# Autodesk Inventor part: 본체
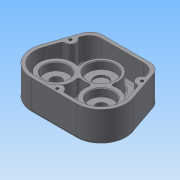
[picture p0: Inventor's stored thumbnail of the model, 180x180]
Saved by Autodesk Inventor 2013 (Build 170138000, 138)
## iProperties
Created: 2014-12
Part Number: 본체
Material: 일반
Document SubType Name: Modeling
Designer: Administrator
Density: 1 g/cm^3
Author: Administrator
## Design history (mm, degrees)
sketch "스케치1"
  geometry: L1 (0, 0)-(-32.527, -32.527); L2 (0, 0)-(32.527, -32.527); L3 (0, 0)-(0, -46); L4 (-47, 36)-(47, 36); L5 (-32.527, -68.527)-(32.527, -68.527); L6 (47, 36)-(66.565, -20.803); L7 (-47, 36)-(-66.565, -20.803); A1 r 46 centre (0, 0) between (-32.527, -32.527) and (32.527, -32.527); A2 r 36 centre (32.527, -32.527) between (32.527, -68.527) and (66.565, -20.803); A3 r 36 centre (-32.527, -32.527) between (-66.565, -20.803) and (-32.527, -68.527); 2 further points
  constraints: 14 end point, 7 point on circle, 3 centre point, 3 coincident, 3 tangent, 1 midpoint, 1 parallel, 1 perpendicular, 1 vertical, 1 vertical alignment
  dimensions: "d2" = 92 diameter of A1; "d3" = 90 deg angle of L2 L1; "d5" = 45 deg angle of L3 L1; "d9" = 94 distance of L4.start L4.end; "d10" = 36 distance from line of L4 point (0, 0)
extrude "돌출1" new body sketch "스케치1" distance "d11" = 44; taper "d12" = 0 deg
fillet "모깎기1" dims "d13" = 18
fillet "모깎기3" dims "d15" = 3
sketch "스케치27"
  geometry: L1 (-66.565, -20.803)-(-51.181, 23.862) reference; L2 (51.181, 23.862)-(66.565, -20.803) reference; L3 (-34.162, 36)-(34.162, 36) reference; L4 (-43.434, 31)-(-61.837, -22.432); L5 (43.434, 31)-(61.837, -22.432); L6 (-32.527, -63.527)-(32.527, -63.527); L7 (-43.434, 31)-(43.434, 31); L8 (-34.162, 36)-(34.162, 36) reference; L9 (51.181, 23.862)-(66.565, -20.803) reference; L10 (32.527, -68.527)-(-32.527, -68.527) reference; L11 (-66.565, -20.803)-(-51.181, 23.862) reference; A1 r 36 centre (-32.527, -32.527) between (-66.565, -20.803) and (-32.527, -68.527) reference; A2 r 36 centre (32.527, -32.527) between (32.527, -68.527) and (66.565, -20.803) reference; A3 r 31 centre (32.527, -32.527) between (32.527, -63.527) and (61.837, -22.432); A4 r 31 centre (-32.527, -32.527) between (-61.837, -22.432) and (-32.527, -63.527); A5 r 18 centre (-34.162, 18) between (-34.162, 36) and (-51.181, 23.862) reference; A6 r 18 centre (34.162, 18) between (51.181, 23.862) and (34.162, 36) reference; A7 r 36 centre (32.527, -32.527) between (32.527, -68.527) and (66.565, -20.803) reference; A8 r 36 centre (-32.527, -32.527) between (-66.565, -20.803) and (-32.527, -68.527) reference; 3 further points
  constraints: 8 end point, 4 point on circle, 4 tangent, 3 coincident, 2 centre point, 2 parallel, 1 midpoint, 1 vertical alignment
  dimensions: "d88" = 62 diameter of A3; "d90" = 62 diameter of A4; "d93" = 5 distance from line of L1 L4.start; "d94" = 5 distance from line of L3 point (0, 31); "d95" = 43.43386 distance of L5.start point (0, 31)
extrude "돌출17" cut sketch "스케치27" distance "d96" = 34; taper "d97" = 0 deg
fillet "모깎기5" dims "d98" = 18
sketch "스케치35"
  geometry: L1 (-61.837, -22.432)-(-47.615, 18.862) reference; L2 (-34.162, 36)-(34.162, 36) reference; A1 r 8 centre (-51.7, 7) between (-54.305, -0.564) and (-49.095, 14.564); 1 further point
  constraints: 3 point on line, 2 point on circle, 1 centre point
  dimensions: "d114" = 16 diameter of A1; "d115" = 29 distance from line of L2 A1.centre
extrude "돌출23" join sketch "스케치35" stored distance "d116" = 3; taper "d117" = 0 deg
sketch "스케치36"
  geometry: L1 (32.527, -63.527)-(-32.527, -63.527) reference; A1 r 8 centre (0, -63.527) between (8, -63.527) and (-8, -63.527); 1 further point
  constraints: 2 point on circle, 2 point on line, 1 centre point, 1 midpoint
  dimensions: "d118" = 16 diameter of A1
extrude "돌출24" join sketch "스케치36" stored distance "d119" = 3; taper "d120" = 0 deg
hole "구멍3" diameter "d123" = 4.134; stored, may be unused: countersink angle "d127" = 90 deg, drill point angle "d129" = 118 deg; dims "d121" = 10, "d122" = 10, "d124" = 20, "d125" = 4, "d126" = 2, "d128" = 23
hole "구멍4" diameter "d132" = 4.134; stored, may be unused: countersink angle "d136" = 90 deg, drill point angle "d138" = 118 deg; dims "d130" = 10, "d131" = 10, "d133" = 20, "d134" = 4, "d135" = 2, "d137" = 23
sketch "스케치37"
  geometry: C1 r 20 at (-32.527, -32.527); A1 r 33 centre (-32.527, -32.527) between (-63.728, -21.78) and (-32.527, -65.527) reference; 1 further point
  constraints: 1 centre point, 1 coincident
  dimensions: "d139" = 40 diameter of C1
extrude "돌출25" join sketch "스케치37" distance "d140" = 7; taper "d141" = -10 deg
sketch "스케치38"
  geometry: C1 r 18.766 at (0, 0) reference; C2 r 15 at (0, 0); 1 further point
  constraints: 1 centre point, 1 coincident
  dimensions: "d142" = 30 diameter of C2
extrude "돌출26" cut sketch "스케치38" distance "d143" = 7; taper "d144" = 0 deg
sketch "스케치39"
  geometry: C1 r 15 at (0, 0) reference; C2 r 7.75 at (0, 0); 1 further point
  constraints: 1 centre point, 1 coincident
  dimensions: "d145" = 15.5 diameter of C2
extrude "돌출27" cut sketch "스케치39" distance "d146" = 10; taper "d147" = 0 deg
sketch "스케치40"
  geometry: C1 r 7.75 at (32.527, -32.527) reference; C2 r 24 at (32.527, -32.527); A1 r 31 centre (32.527, -32.527) between (32.527, -63.527) and (61.837, -22.432) reference; 1 further point
  constraints: 1 centre point, 1 coincident
  dimensions: "d148" = 48 diameter of C2
extrude "돌출28" join sketch "스케치40" distance "d149" = 23; taper "d150" = 0 deg
sketch "스케치41"
  geometry: C1 r 7.75 at (0, 0) reference; C2 r 24 at (0, 0) reference; C3 r 17.5 at (0, 0); 1 further point
  constraints: 1 centre point, 1 coincident
  dimensions: "d151" = 35 diameter of C3
extrude "돌출29" cut sketch "스케치41" distance "d152" = 11; taper "d153" = 0 deg
sketch "스케치42"
  geometry: C1 r 24 at (0, 0); 1 further point
  constraints: 1 centre point, 1 coincident
  dimensions: "d154" = 48 diameter of C1
extrude "돌출30" join sketch "스케치42" distance "d155" = 23; taper "d156" = 0 deg
sketch "스케치43"
  geometry: C1 r 20 at (0, 0); A1 r 24 centre (0, 0) between (21.111, -11.416) and (11.416, -21.111) reference
  constraints: 1 centre point, 1 coincident
  dimensions: "d157" = 40 diameter of C1
extrude "돌출31" cut sketch "스케치43" distance "d158" = 11; taper "d159" = 0 deg
sketch "스케치44"
  geometry: C1 r 20 at (0, 0) reference; C2 r 10 at (0, 0)
  constraints: 1 centre point, 1 coincident
  dimensions: "d160" = 20 diameter of C2
extrude "돌출32" cut sketch "스케치44" distance "d161" = 3; taper "d162" = 0 deg
sketch "스케치45"
  geometry: C1 r 24 at (-32.527, -32.527); A1 r 31 centre (-32.527, -32.527) between (-61.837, -22.432) and (-32.527, -63.527) reference
  constraints: 1 centre point, 1 coincident
  dimensions: "d163" = 48 diameter of C1
extrude "돌출33" join sketch "스케치45" distance "d164" = 23; taper "d165" = 0 deg
sketch "스케치46"
  geometry: C1 r 17.5 at (-32.527, -32.527); A1 r 24 centre (-32.527, -32.527) between (-21.111, -11.416) and (-11.416, -21.111) reference
  constraints: 1 centre point, 1 coincident
  dimensions: "d166" = 35 diameter of C1
extrude "돌출34" cut sketch "스케치46" distance "d167" = 11; taper "d168" = 0 deg
sketch "스케치47"
  geometry: C1 r 20 at (32.527, -32.527); A1 r 33 centre (32.527, -32.527) between (32.527, -65.527) and (63.728, -21.78) reference; 1 further point
  constraints: 1 centre point, 1 coincident
  dimensions: "d169" = 40 diameter of C1
extrude "돌출35" join sketch "스케치47" distance "d170" = 7; taper "d171" = -10 deg
sketch "스케치48"
  geometry: C1 r 18.766 at (0, 0) reference; C2 r 15 at (0, 0); 1 further point
  constraints: 1 centre point, 1 coincident
  dimensions: "d172" = 30 diameter of C2
extrude "돌출36" cut sketch "스케치48" distance "d173" = 7; taper "d174" = 0 deg
sketch "스케치49"
  geometry: C1 r 15 at (0, 0) reference; C2 r 7.75 at (0, 0); 1 further point
  constraints: 1 centre point, 1 coincident
  dimensions: "d175" = 15.5 diameter of C2
extrude "돌출37" cut sketch "스케치49" stored distance "d176" = 10; taper "d177" = 0 deg
fillet "모깎기6" dims "d178" = 3
fillet "모깎기7" dims "d179" = 3
fillet "모깎기8" dims "d180" = 3
fillet "모깎기9" dims "d181" = 3
fillet "모깎기10" dims "d182" = 3
chamfer "모따기1" distance "d183" = 1; stored, may be unused: second distance "d184" = 2, angle "d185" = 45 deg
fillet "모깎기11" dims "d186" = 0.3
fillet "모깎기12" dims "d187" = 0.1
chamfer "모따기2" distance "d188" = 1; stored, may be unused: second distance "d189" = 2, angle "d190" = 45 deg
sketch "스케치50"
  geometry: L1 (34.162, 36)-(-34.162, 36) reference; 2 further points
  constraints: 1 vertical alignment, 1 other
  dimensions: "d191" = 30 distance from line of L1 point (0, 6)
feature "엠보싱1" sketch "스케치50" dims "d2" = 92, "d192" = 1, "d193" = 0
node "솔리드1"
mirror "대칭3"
node "절단 모서리 투영5"
other parameters: "d7" = 72, "d8" = 72
